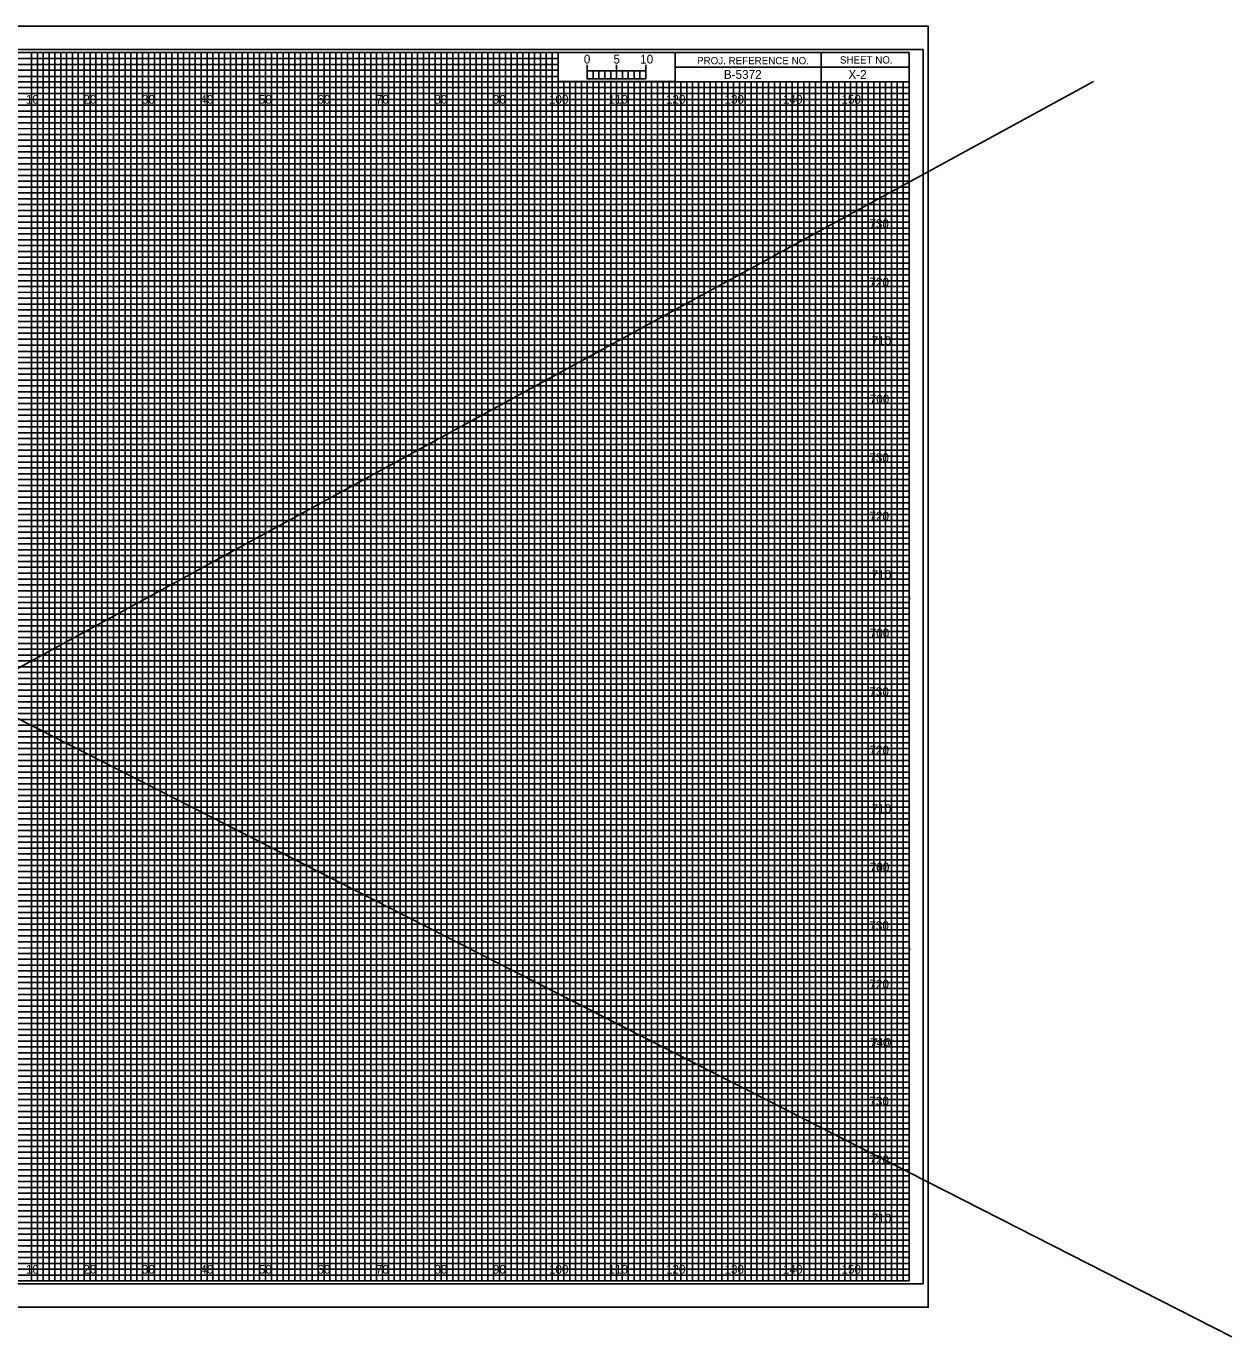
# Model space of a CAD drawing. Extents: x -98 to 717, y -10 to 1974.
# Drawn here: x 169.1 to 375.2, y -9.5 to 214.5 of the extents above; entities that cross this region are included whole.
import ezdxf

# ---------------------------------------------------------------- set-up
doc = ezdxf.new("R2010")
doc.units = 0
for name, color, linetype in [('Default', 7, 'Continuous'), ('Exist XS Center Line Elevation Label', 7, 'Continuous'), ('Prop CMT Conc Surface', 7, 'Continuous'), ('Prop CMT Concrete Structures', 7, 'Continuous'), ('Prop CMT Pvmt Course 1 CG', 7, 'Continuous'), ('Prop CMT Pvmt Course 2', 7, 'Continuous'), ('Prop CMT Pvmt Course 3', 7, 'Continuous'), ('Prop CMT Pvmt Surface', 7, 'Continuous'), ('Prop CMT Pvmt Surface Shoulder', 7, 'Continuous'), ('Prop CMT Shld Paved Course 1', 7, 'Continuous'), ('Prop CMT Shld Paved Course 2', 7, 'Continuous'), ('Prop CMT Slope Grass', 7, 'Continuous'), ('Prop CMT Subgrade Earthwork', 7, 'Continuous'), ('Prop XS Earthwork Shape', 7, 'Continuous'), ('Prop XS Elevation Labels', 7, 'Continuous'), ('Typical Curb CELL', 7, 'Continuous')]:
    doc.layers.add(name, color=color, linetype=linetype)

msp = doc.modelspace()

# ---------------------------------------------------------------- linework, layer by layer
at = {"layer": 'Default'}
for p, q in [((351.51, 205.03), (-41.86, -9.54)), ((-40.39, 202.07), (375.17, -9.54))]:
    msp.add_line(p, q, dxfattribs=at)
at = {"layer": 'Exist XS Center Line Elevation Label'}
for p, q in [((0, 209), (260, 209)), ((260, 209), (260, 207.98)), ((260, 207.98), (0, 207.98)), ((0, 207), (260, 207)), ((260, 207), (260, 205.89)), ((260, 205.89), (0, 205.89)), ((0, 204), (320, 204))]:
    msp.add_line(p, q, dxfattribs=at)
for points in [[(0, 203), (270, 203), (320, 203), (320, 202), (0, 202)], [(0, 201), (320, 201), (320, 199), (0, 199)], [(0, 198), (320, 198), (320, 197), (0, 196.98)], [(0, 196), (320, 196), (320, 194), (0, 194)], [(0, 193), (320, 193), (320, 192), (0, 192)], [(0, 191), (320, 191), (320, 189), (0, 189)], [(0, 188), (320, 188), (320, 187), (0, 187)], [(0, 186), (320, 186), (320, 184), (0, 184)], [(0, 183), (320, 183), (320, 182), (0, 182)], [(0, 181), (320, 181), (320, 179), (0, 179)], [(0, 178), (320, 178), (320, 177), (0, 177)], [(0, 176), (320, 176), (320, 173.95), (320, 173), (320, 172), (0, 172)], [(0, 174), (320, 174), (320, 173), (0, 173)], [(0, 171), (320, 171), (320, 169), (0, 169.03)], [(0, 169.03), (320, 169), (320, 168), (0, 168)], [(0, 167), (320, 167), (320, 166), (0, 166)], [(0, 164), (320, 164), (320, 163), (0, 163)], [(0, 162), (320, 162), (320, 161), (0, 161)], [(-0.07, 158.89), (320, 158.89), (320, 157.88), (-0.07, 157.88)], [(0, 157), (320, 157), (320, 156), (0, 156)], [(0, 154), (320, 154), (320, 153), (0, 153)], [(0, 152), (320, 152), (320, 151), (0, 151)], [(0, 149), (320, 149), (320, 148), (0, 148)], [(0, 147), (320, 147), (320, 146), (0, 146)], [(0, 144), (320, 144), (320, 143), (0, 143)], [(0, 142), (320, 142), (320, 141), (0, 141)], [(0, 139), (320, 139), (319.99, 137.98), (0, 138)], [(0, 137), (320, 137), (320, 136), (0, 136)], [(0, 134), (320, 134), (320, 133), (0, 133)], [(0, 132), (320, 132), (320, 131), (0, 131)], [(0, 129), (320, 129), (320, 128), (0, 128)], [(0, 127), (320, 127), (320, 126), (0, 126)], [(0, 124), (320, 124), (320, 123), (0, 123)], [(0, 122), (320, 122), (320, 121), (0, 121)], [(0, 119), (320, 119), (320, 118), (0, 118)], [(0, 116.99), (320.07, 116.91), (320, 116), (0, 116)], [(0, 114), (320, 114), (320, 113), (0, 113)], [(0, 112), (320, 112), (320, 111), (0, 111)], [(0, 109), (320, 109), (320, 108), (0, 108)], [(0, 107), (320, 107), (320, 106), (0, 106)], [(0, 104), (320, 104), (320, 103), (0, 103)], [(0, 102), (320, 102), (320, 101), (0, 101)], [(0, 99), (320, 99), (320, 98), (0, 98)], [(0, 97), (320, 97), (320, 96), (0, 96)], [(0, 94), (320, 94), (320, 93), (0, 93)], [(0, 92), (320, 92), (320, 91), (0, 91)], [(0, 89), (320, 89), (320, 88), (0, 88)], [(0, 87), (320, 87), (320, 86), (0, 86)], [(0, 84), (320, 84), (320, 83), (0, 83)], [(0, 82), (320, 82), (320, 81), (0, 81)], [(0, 79), (320, 79), (319.99, 77.98), (0, 78)], [(0, 77), (320, 77), (320, 76), (0, 76)], [(0, 74), (320, 74), (320, 73), (0, 73)], [(0, 72), (320, 72), (320, 71), (0, 71)], [(0, 69), (320, 69), (320, 68), (0, 68)], [(0, 67), (320, 67), (320, 66), (0, 66)], [(0, 64), (320, 64), (320, 63), (0, 63)], [(0, 62), (320, 62), (320, 61), (0, 61)], [(0, 59), (320, 59), (320, 58), (0, 58)], [(0, 56.99), (320.07, 56.91), (320, 56), (0, 56)], [(0, 54), (320, 54), (320, 53), (0, 53)], [(0, 52), (320, 52), (320, 51), (0, 51)], [(0, 49), (320, 49), (320, 48), (0, 48)], [(0, 47), (320, 47), (320, 46), (0, 46)], [(0, 44), (320, 44), (320, 43), (0, 43)], [(0, 42), (320, 42), (320, 41), (0, 41)], [(0, 39), (320, 39), (320, 38), (0, 38)], [(0, 37), (320, 37), (320, 36), (0, 36)], [(0, 34), (320, 34), (320, 33), (0, 33)], [(0, 32), (320, 32), (320, 31), (0, 31)], [(0, 29), (320, 29), (320, 28), (0, 28)], [(0, 27), (320, 27), (320, 26), (0, 26)], [(0, 24), (320, 24), (320, 23), (0, 23)], [(0, 22), (320, 22), (320, 21), (0, 21)], [(0, 19), (320, 19), (320, 18), (0, 18)], [(0, 17), (320, 17), (320, 16), (0, 16)], [(0, 14), (320, 14), (320, 13), (0, 13)], [(0, 12), (320, 12), (320, 11), (0, 11)], [(0, 9), (320, 9), (320, 8), (0, 8)], [(0, 7), (320, 7), (320, 6), (0, 6)], [(0, 4), (320, 4), (320, 3), (0, 3)], [(0, 2), (320, 2), (320, 1), (0, 1)]]:
    msp.add_lwpolyline(points, dxfattribs=at)
at = {"layer": 'Prop CMT Conc Surface'}
for p, q in [((305, 210), (305, 205)), ((305, 205), (305, 210)), ((280, 207.5), (280, 205)), ((320, 207.49), (280, 207.49)), ((280, 205), (320, 205))]:
    msp.add_line(p, q, dxfattribs=at)
for points in [[(320, 210), (0, 210), (0, 0), (320, 0)], [(280, 210), (260, 210), (260, 205.03), (280, 205.03)], [(320, 210), (280, 210), (280, 205), (320, 205)]]:
    msp.add_lwpolyline(points, close=True, dxfattribs=at)
at = {"layer": 'Prop CMT Concrete Structures'}
for p, q in [((170, 0), (170, 210)), ((180, 0), (180, 210)), ((190, 0), (190, 210)), ((200, 0), (200, 210)), ((210, 0), (210, 210)), ((220, 0), (220, 210)), ((230, 0), (230, 210)), ((240, 0), (240, 210)), ((250, 0), (250, 210)), ((260, 0), (260, 204.69)), ((270, 0), (270, 204.69)), ((280, 0), (280, 204.69)), ((290, 0), (290, 204.69)), ((300, 0), (300, 204.69)), ((310, 0), (310, 204.69)), ((0, 200), (320, 200)), ((0, 190), (320, 190)), ((0, 180), (320, 180)), ((0, 170), (320, 170)), ((0, 160), (320, 160)), ((0, 150), (320, 150)), ((0, 140), (320, 140)), ((0, 130), (320, 130)), ((0, 120), (320, 120)), ((0, 110), (320, 110)), ((0, 100), (320, 100)), ((0, 90), (320, 90)), ((0, 80), (320, 80)), ((0, 70), (320, 70)), ((0, 60), (320, 60)), ((0, 50), (320, 50)), ((0, 40), (320, 40)), ((0, 30), (320, 30)), ((0, 20), (320, 20)), ((0, 10), (320, 10))]:
    msp.add_line(p, q, dxfattribs=at)
at = {"layer": 'Prop CMT Pvmt Course 2'}
msp.add_lwpolyline([(-13.4, -4.5), (323.3, -4.5), (323.3, 214.5), (-13.4, 214.5)], close=True, dxfattribs=at)
at = {"layer": 'Prop CMT Pvmt Course 3'}
msp.add_lwpolyline([(-10.8, -0.5), (322.4, -0.5), (322.4, 210.5), (-10.8, 210.5)], close=True, dxfattribs=at)
at = {"layer": 'Prop CMT Pvmt Surface'}
for p, q in [((323.3, 214.5), (-13.4, 214.5)), ((-13.4, -4.5), (323.3, -4.5))]:
    msp.add_line(p, q, dxfattribs=at)
at = {"layer": 'Prop CMT Slope Grass'}
for p, q in [((265, 205.49), (265, 207.9)), ((265, 206.9), (265, 207.9)), ((270, 205.49), (270, 207.9)), ((275, 205.49), (275, 207.9)), ((275, 206.9), (275, 207.9))]:
    msp.add_line(p, q, dxfattribs=at)
for points in [[(275, 206.9), (265, 206.9), (265, 205.49), (275, 205.49)], [(265, 206.9), (266, 206.9), (266, 205.49), (265, 205.49)], [(267, 206.9), (268, 206.9), (268, 205.49), (267, 205.49)], [(269, 206.9), (270, 206.9), (270, 205.49), (269, 205.49)], [(271, 206.9), (272, 206.9), (272, 205.49), (271, 205.49)], [(273, 206.9), (274, 206.9), (274, 205.49), (273, 205.49)]]:
    msp.add_lwpolyline(points, close=True, dxfattribs=at)
at = {"layer": 'Prop CMT Subgrade Earthwork'}
for p, q in [((267, 205), (266.01, 205)), ((266.01, 205), (266.01, 0)), ((267, 0), (267, 205)), ((269, 205), (268, 205)), ((268, 205), (268, 0)), ((269, 0), (269, 205)), ((266.01, 0), (265, 0)), ((268, 0), (267, 0))]:
    msp.add_line(p, q, dxfattribs=at)
for points in [[(170, 0), (171, 0), (171, 210), (172, 210), (172, 0)], [(172, 0), (173, 0), (173, 210), (174, 210), (174, 0)], [(175, 0), (176, 0), (176, 210), (177, 210), (177, 0)], [(177, 0), (178, 0), (178, 210), (179, 210), (179, 0)], [(180, 0), (181, 0), (181, 210), (182, 210), (182, 0)], [(182, 0), (183, 0), (183, 210), (184, 210), (184, 0)], [(185, 0), (186, 0), (186, 210), (187, 210), (187, 0)], [(187, 0), (188, 0), (188, 210), (189, 210), (189, 0)], [(190, 0), (191, 0), (191, 210), (192, 210), (192, 0)], [(192, 0), (193, 0), (193, 210), (194, 210), (194, 0)], [(195, 0), (196, 0), (196, 210), (197, 210), (197, 0)], [(197, 0), (198, 0), (198, 210), (199, 210), (199, 0)], [(200, 0), (201, 0), (201, 210), (202, 210), (202, 0)], [(202, 0), (203, 0), (203, 210), (204, 210), (204, 0)], [(205, 0), (206, 0), (206, 210), (207, 210), (207, 0)], [(207, 0), (208, 0), (208, 210), (209, 210), (209, 0)], [(210, 0), (211, 0), (211, 210), (212, 210), (212, 0)], [(212, 0), (213, 0), (213, 210), (214, 210), (214, 0)], [(215, 0), (216, 0), (216, 210), (217, 210), (217, 0)], [(217, 0), (218, 0), (218, 210), (219, 210), (219, 0)], [(220, 0), (221, 0), (221, 210), (222, 210), (222, 0)], [(222, 0), (223, 0), (223, 210), (224, 210), (224, 0)], [(225, 0), (226, 0), (226, 210), (227, 210), (227, 0)], [(227, 0), (228, 0), (228, 210), (229, 210), (229, 0)], [(230, 0), (231, 0), (231, 210), (232, 210), (232, 0)], [(232, 0), (233, 0), (233, 210), (234, 210), (234, 0)], [(235, 0), (236, 0), (236, 210), (237, 210), (237, 0)], [(237, 0), (238, 0), (238, 210), (239, 210), (239, 0)], [(240, 0), (241, 0), (241, 210), (242, 210), (242, 0)], [(242, 0), (243, 0), (243, 210), (244, 210), (244, 0)], [(245, 0), (246, 0), (246, 210), (247, 210), (247, 0)], [(247, 0), (248, 0), (248, 210), (249, 210), (249, 0)], [(250, 0), (251, 0), (251, 210), (252, 210), (252, 0)], [(252, 0), (253, 0), (253, 210), (254, 210), (254, 0)], [(255, 0), (256, 0), (256, 210), (257, 210), (257, 0)], [(257, 0), (258, 0), (258, 210), (259, 210), (259, 0)], [(260, 0), (261, 0), (261, 205), (262.02, 205), (262.02, 0)], [(262, 0), (263, 0), (263, 205), (263.99, 205), (263.99, 0)], [(270, 0), (270.98, 0), (270.98, 205), (272, 205), (272, 0)], [(272, 0), (273, 0), (273, 205), (274.05, 205), (274.05, 0)], [(275, 0), (276, 0), (276, 205), (277, 205), (277, 0)], [(277, 0), (278, 0), (278, 205), (279, 205), (279, 0)], [(280, 0), (281, 0), (281, 205), (282, 205), (282, 0)], [(282, 0), (283, 0), (283, 205), (284, 205), (284, 0)], [(285, 0), (286, 0), (286, 205), (287, 205), (287, 0)], [(287, 0), (288, 0), (288, 205), (289, 205), (289, 0)], [(290, 0), (291, 0), (291, 205), (292, 205), (292, 0)], [(292, 0), (293, 0), (293, 205), (294, 205), (294, 0)], [(295, 0), (296, 0), (296, 205), (297, 205), (297, 0)], [(297, 0), (298, 0), (298, 205), (299, 205), (299, 0)], [(300, 0), (301, 0), (301, 205), (302, 205), (302, 0)], [(302, 0), (303, 0), (303, 205), (304, 205), (304, 0)], [(305, 0), (306, 0), (306, 205), (307, 205), (307, 0)], [(307, 0), (308, 0), (308, 205), (309, 205), (309, 0)], [(310, 0), (311, 0), (311, 205), (312, 205), (312, 0)], [(312, 0), (313, 0), (313, 205), (314, 205), (314, 0)], [(315, 0), (316, 0), (316, 205), (317, 205), (317, 0)], [(317, 0), (318, 0), (318, 205), (319, 205), (319, 0)]]:
    msp.add_lwpolyline(points, dxfattribs=at)
at = {"layer": 'Prop XS Elevation Labels'}
for p, q in [((170, 210), (160, 210)), ((170, 0), (170, 210)), ((190, 210), (180, 210)), ((180, 210), (180, 0)), ((190, 0), (190, 210)), ((210, 210), (200, 210)), ((200, 210), (200, 0)), ((210, 0), (210, 210)), ((230, 210), (220, 210)), ((220, 210), (220, 0)), ((230, 0), (230, 210)), ((250, 210), (240, 210)), ((240, 210), (240, 0)), ((250, 0), (250, 210)), ((260, 210), (260, 0)), ((270, 0), (270, 205)), ((290, 205), (280, 205)), ((280, 205), (280, 0)), ((290, 0), (290, 205)), ((310, 205), (300, 205)), ((300, 205), (300, 0)), ((310, 0), (310, 205)), ((180, 0), (170, 0)), ((200, 0), (190, 0)), ((220, 0), (210, 0)), ((240, 0), (230, 0)), ((260, 0), (250, 0)), ((280, 0), (270, 0)), ((300, 0), (290, 0)), ((320, 0), (310, 0)), ((320, 0), (320, 0))]:
    msp.add_line(p, q, dxfattribs=at)
for points in [[(0, 200), (320, 200), (320, 190), (0, 190)], [(0, 180), (320, 180), (320, 170), (0, 170)], [(0, 160), (320, 160), (320, 150), (0, 150)], [(0, 140), (320, 140), (320, 130), (0, 130)], [(0, 120), (320, 120), (320, 110), (0, 110)], [(0, 100), (320, 100), (320, 90), (0, 90)], [(0, 80), (320, 80), (320, 70), (0, 70)], [(0, 60), (320, 60), (320, 50), (0, 50)], [(0, 40), (320, 40), (320, 30), (0, 30)], [(0, 20), (320, 20), (320, 10), (0, 10)]]:
    msp.add_lwpolyline(points, dxfattribs=at)
at = {"layer": 'Typical Curb CELL'}
for points in [[(165, 0), (175, 0), (175, 210), (185, 210), (185, 0), (195, 0), (195, 210), (205, 210), (205, 0), (215, 0), (215, 210), (225, 210), (225, 0), (235, 0), (235, 210), (245, 210), (245, 0), (255, 0), (255, 210), (259.93, 210), (260, 210), (260, 205), (264.99, 205), (264.99, 0), (275, 0), (275, 205), (285, 205), (285, 0), (295, 0), (295, 205), (305, 205), (305, 0), (315, 0), (315, 205)], [(0, 205), (275, 205)], [(0, 185), (320, 185), (320, 195), (0, 195)], [(0, 165), (320, 165), (320, 175), (0, 175)], [(0, 145), (320, 145), (320, 155), (0, 155)], [(0, 125), (320, 125), (320, 135), (0, 135)], [(0, 105), (320, 105), (320, 115), (0, 115)], [(0, 85), (320, 85), (320, 95), (0, 95)], [(0, 65), (320, 65), (320, 75), (0, 75)], [(0, 45), (320, 45), (320, 55), (0, 55)], [(0, 25), (320, 25), (320, 35), (0, 35)], [(0, 5), (320, 5), (320, 15), (0, 15)]]:
    msp.add_lwpolyline(points, dxfattribs=at)

# ---------------------------------------------------------------- texts
at = {"layer": 'Prop CMT Conc Surface'}
for s, p in [('PROJ. REFERENCE NO.', (283.77, 207.99)), ('SHEET NO.', (308.19, 208.12))]:
    msp.add_text(s, height=1.25, dxfattribs=at).set_placement(p)
at = {"layer": 'Prop CMT Pvmt Course 1 CG'}
for s, p in [('730', (313.22, 180)), ('720', (313.23, 170)), ('710', (313.61, 160)), ('700', (313.28, 150)), ('730', (313.22, 140)), ('720', (313.23, 130)), ('710', (313.61, 120)), ('700', (313.28, 110)), ('730', (313.22, 100)), ('720', (313.23, 90)), ('710', (313.61, 80)), ('700', (313.28, 70)), ('740', (313.3, 70)), ('730', (313.22, 60)), ('720', (313.23, 50)), ('740', (313.3, 40)), ('710', (313.61, 40)), ('730', (313.22, 30)), ('720', (313.23, 20)), ('710', (313.61, 10))]:
    msp.add_text(s, height=1.5, dxfattribs=at).set_placement(p)
at = {"layer": 'Prop CMT Pvmt Surface Shoulder'}
for s, p in [('5', (269.47, 208.12)), ('10', (274.04, 208.12))]:
    msp.add_text(s, height=1.5, dxfattribs=at).set_placement(p)
at = {"layer": 'Prop CMT Shld Paved Course 1'}
msp.add_text('X-2', height=1.5, dxfattribs=at).set_placement((309.64, 205.5))
at = {"layer": 'Prop CMT Shld Paved Course 2'}
msp.add_text('B-5372', height=1.5, dxfattribs=at).set_placement((288.34, 205.5))
at = {"layer": 'Prop CMT Slope Grass'}
msp.add_text('0', height=1.5, dxfattribs=at).set_placement((264.41, 208.12))
at = {"layer": 'Prop XS Earthwork Shape'}
for s, p in [('10', (169.04, 201.25)), ('20', (178.86, 201.25)), ('30', (188.86, 201.25)), ('40', (198.86, 201.25)), ('50', (208.86, 201.25)), ('60', (218.86, 201.25)), ('70', (228.86, 201.25)), ('80', (238.86, 201.25)), ('90', (248.86, 201.25)), ('100', (258.44, 201.25)), ('110', (268.62, 201.25)), ('120', (278.44, 201.25)), ('130', (288.44, 201.25)), ('140', (298.44, 201.25)), ('150', (308.44, 201.25)), ('10', (169.04, 1.25)), ('20', (178.86, 1.25)), ('30', (188.86, 1.25)), ('40', (198.86, 1.25)), ('50', (208.86, 1.25)), ('60', (218.86, 1.25)), ('70', (228.86, 1.25)), ('80', (238.86, 1.25)), ('90', (248.86, 1.25)), ('100', (258.44, 1.25)), ('110', (268.62, 1.25)), ('120', (278.44, 1.25)), ('130', (288.44, 1.25)), ('140', (298.44, 1.25)), ('150', (308.44, 1.25))]:
    msp.add_text(s, height=1.5, dxfattribs=at).set_placement(p)

doc.saveas('drawing.dxf')
